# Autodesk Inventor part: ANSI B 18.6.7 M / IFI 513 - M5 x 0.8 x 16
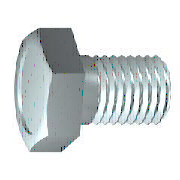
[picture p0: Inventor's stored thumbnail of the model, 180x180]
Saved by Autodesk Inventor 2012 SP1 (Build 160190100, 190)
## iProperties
Created: 2006-02
Part Number: ANSI B 18.6.7 M / IFI 513 - M5 x 0.8 x 16
Material: Steel, Mild
Description: Indented Hex Head Machine Screw
Document SubType Name: Modeling
Standard: ANSI B 18.6.7 M / IFI 513
Standards Organization: ANSI
Language: en-US
Size Designation: M5 x 0.8 x 16
Categories: <MemberInstance><Categories><Category DisplayName="Fasteners" InternalName="e4da775c-781d-43d5-af7c-5136215cf5a6" Mnemonic="FSTN"><Category DisplayName="Bolts"
Mass: 3.83757 g
Surface Area: 4.77388 cm^2
Volume: 0.48824 cm^3
Density: 7.86 g/cm^3
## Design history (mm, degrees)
workplane "Work Plane1"
sketch "Sketch3"
  geometry: C1 r 3.25 at (0, 0); 1 further point
  constraints: 1 centre point, 1 coincident
  dimensions: "d18" = 6.5 diameter of C1 (= KOD2)
extrude "Indent" cut sketch "Sketch3" distance "d19" = 0.761 (computed from KOH2); taper "d20" = 0 deg
revolve "Body" stored, may be unused: angle "d12" = 90 deg
sketch "Sketch2"
  geometry: L1 (0, 4.619)-(4, 2.309); L2 (4, 2.309)-(4, -2.309); L3 (4, -2.309)-(0, -4.619); L4 (0, -4.619)-(-4, -2.309); L5 (-4, -2.309)-(-4, 2.309); L6 (-4, 2.309)-(0, 4.619); 3 further points
  constraints: 12 end point, 2 coincident, 1 vertical, 11 other
  dimensions: "d8" = 8 distance between parallel lines of L5 L2 (= SW)
extrude "Head" join sketch "Sketch2" distance "d2" = 3.8 (= KOH - SD); taper "d3" = 0 deg
revolve "Chamfer1" stored, may be unused: angle "d21" = 90 deg
body "Solid1"
feature "Thread" dims "d9" = 14 (= GEL), "d10" = 0
chamfer "Chamfer2" distance "d5" = 0.7 (= -0.5 x SPD + 0.5 x GD); stored, may be unused: second distance "d6" = 0.49086 (computed from GUL), angle "d77" = 45 deg
sketch "Sketch1"
  geometry: L1 (2, 2.5)-(16, 2.5); L2 (16, 2.5)-(16, 0); L3 (16, 0)-(0, 0); L4 (0, 0)-(0, 2.18); L5 (0, 2.18)-(1.509, 2.18); L6 (1.509, 2.18)-(2, 2.5); L7 (0, -0.25)-(0, 3.25) reference; L8 (-1.6, 0)-(20.8, 0) reference
  constraints: 12 end point, 2 collinear, 2 perpendicular
  dimensions: "d0" = 14 distance from line of L1.start L2 (= GEL); "d1" = 5 diameter of L1 L3 (= GD); "d13" = 16 distance between parallel lines of L2 L4 (= NLG); "d14" = 0.49076 horizontal distance of L5.end L1.start (= GAL); "d16" = 4.36 diameter of L4.end L3 (= BDM)
sketch "Sketch4"
  geometry: L1 (-3.8, 4)-(-3.8, 4.619); L2 (-3.8, 4.619)-(-3.443, 4.619); L3 (-3.443, 4.619)-(-3.8, 4); L4 (-4.18, 0)-(1.14, 0) reference; L5 (0, 4.619)-(-3.8, 4.619) reference; L6 (-3.8, 2.309)-(-3.8, 4.619) reference
  constraints: 6 end point, 2 collinear, 1 perpendicular, 1 vertical
  dimensions: "d4" = 30 deg angle of L3 L1 (= ANG1); "d17" = 8 diameter of L1.start L4 (= SW)
other parameters: "NLG" = 16 [user parameter; used in 1 equation term], "GD" = 5 (= NND) [user parameter; used in 2 equation terms], "BDM" = 4.36 [user parameter; used in 1 equation term], "KOH" = 3.8 [user parameter; used in 1 equation term], "GEL" = 14 [user parameter; used in 2 equation terms], "SW" = 8 [user parameter; used in 3 equation terms], "SPD" = 3.6 [user parameter; used in 1 equation term], "SD" = 0 [user parameter; used in 1 equation term], "ANG1" = 30 deg [user parameter; used in 1 equation term], "GAL" = 0.49076 (= 0.61345 x PTC) [user parameter; used in 1 equation term], "GUL" = 0.49076 (= 0.61345 x PTC) [user parameter; used in 1 equation term], "d7" = 0, "KOH2" = 0.76 [user parameter; used in 1 equation term], "KOD2" = 6.5 [user parameter; used in 1 equation term], "d79" = 0, "d80" = 0, "TPU" = 12.5 (computed from PTC) [user parameter], "GD1" = 4.01848 (= THREADDIA - 1.2269 x PTC) [user parameter], "THREADDIA" = 5 [user parameter; used in 1 equation term], "TOA" = 30 deg [user parameter], "RR" = 0.2 [user parameter], "PTC" = 0.8 [user parameter; used in 4 equation terms], "NND" = 5 [user parameter; used in 1 equation term], "E0" = 9.24 (= 1.155 x SW) [user parameter]
